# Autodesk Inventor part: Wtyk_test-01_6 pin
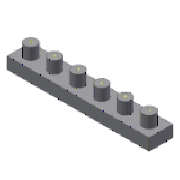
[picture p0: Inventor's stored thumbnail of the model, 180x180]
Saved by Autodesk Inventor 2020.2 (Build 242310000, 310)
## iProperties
Manager: www.cadconsulting.pl
Company: Fabian Stasiak CAD Consulting
Created: 2014-09
Part Number: Wtyk_test-01_6 pin
Material: Ogólny
Document SubType Name: Modeling
Designer: F.Stasiak
Language: pl-PL
Size Designation: 6-Wtyk_test-01_6 pin
Categories: <MemberInstance><Categories><Category DisplayName="Kable i wiązki przewodów" InternalName="e4a7e005-5e42-4d16-b293-125e7f0d0512" Mnemonic="CABLEANDHARNESS"><Cat
Density: 1 g/cm^3
Appearance: Domyślna
Catalog Web Link: www.expertbooks.pl
IsCustomPart: 0
Author: F.Stasiak
Subject: Zbiór ćwiczeń. Autodesk Inventor 2020. Kurs Professional
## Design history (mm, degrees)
sketch "Szkic1"
  geometry: L1 (0, 0)-(60, 0); L2 (0, 5)-(60, 5); L3 (60, 5)-(60, -5); L4 (60, -5)-(0, -5); L5 (0, -5)-(0, 5); 7 further points
  constraints: 10 end point, 2 horizontal, 2 parallel, 1 coincident, 1 midpoint, 1 perpendicular
  dimensions: "d0" = 10 distance of point (15, 0) point (5, 0); "d1" = 10 distance of point (25, 0) point (15, 0) (= d0); "d2" = 10 distance of point (35, 0) point (25, 0) (= d0); "d3" = 10 distance of point (45, 0) point (35, 0) (= d0); "d4" = 10 distance of point (45, 0) point (55, 0) (= d0); "d16" = 5 distance of point (5, 0) L1.start; "d17" = 5 distance of point (55, 0) L1.end (= d16); "d18" = 10 distance of L4.end L2.start; "d19" = 60 distance of L3.end L4.end (= LPINÓW)
node "Oś konstrukcyjna1"
node "Oś konstrukcyjna2"
node "Oś konstrukcyjna3"
node "Oś konstrukcyjna4"
node "Oś konstrukcyjna5"
node "Oś konstrukcyjna6"
extrude "Wyciągnięcie proste3" new body sketch "Szkic1" distance "d20" = 5; taper "d21" = 0 deg
sketch "Szkic3"
  geometry: C1 r 2.5 at (5, 0); 2 further points
  constraints: 1 centre point, 1 coincident
  dimensions: "d22" = 5 diameter of C1
extrude "Wyciągnięcie proste4" join sketch "Szkic3" distance "d23" = 5; taper "d24" = 0 deg
pattern_linear "Szyk prostokątny2" dims "d27" = 10
node "Płaszczyzna konstrukcyjna1"
node "Punkt konstrukcyjny2"
node "Punkt konstrukcyjny3"
node "Punkt konstrukcyjny4"
node "Punkt konstrukcyjny5"
node "Punkt konstrukcyjny6"
node "Punkt konstrukcyjny7"
node "1"
node "2"
node "3"
node "4"
node "5"
node "6"
node "Bryła2"
other parameters: "LPINÓW" = 60 [user parameter; used in 2 equation terms]
